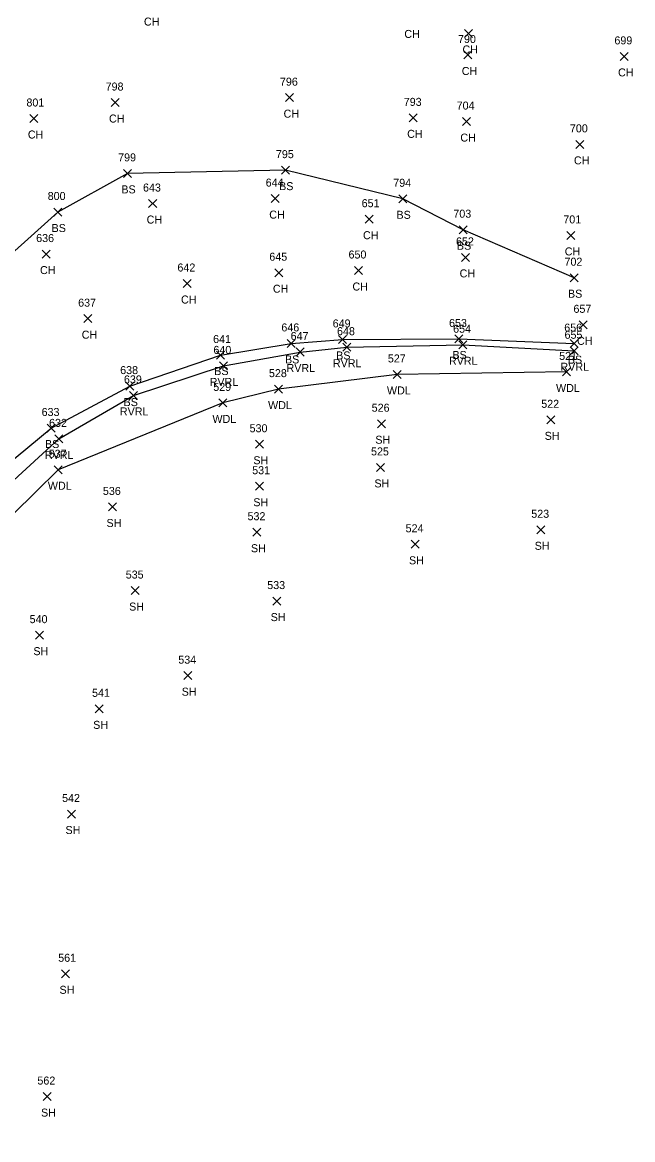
# Model space of a CAD drawing. Extents: x 1885914 to 1887218, y 756253 to 760620.
# Drawn here: x 1886903.9 to 1887056.2, y 759675.3 to 759954.5 of the extents above; entities that cross this region are included whole.
import ezdxf

# ---------------------------------------------------------------- set-up
doc = ezdxf.new("R2010")
doc.units = 0
for name, color, linetype in [('L_A', 7, 'Continuous'), ('L_I', 7, 'Continuous'), ('L_TIC', 7, 'Continuous'), ('LAWA', 7, 'Continuous'), ('LAWE', 7, 'Continuous'), ('LELB', 7, 'Continuous')]:
    doc.layers.add(name, color=color, linetype=linetype)

msp = doc.modelspace()

# ---------------------------------------------------------------- linework, layer by layer
at = {"layer": 'L_TIC'}
for points in [[(1887014.25, 759950.7), (1887016.25, 759952.7)], [(1887016.25, 759950.7), (1887014.25, 759952.7)], [(1887014.08, 759945.32), (1887016.08, 759947.32)], [(1887016.08, 759945.32), (1887014.08, 759947.32)], [(1887053.08, 759944.97), (1887055.08, 759946.97)], [(1887055.08, 759944.97), (1887053.08, 759946.97)], [(1886926.02, 759933.44), (1886928.02, 759935.44)], [(1886928.02, 759933.44), (1886926.02, 759935.44)], [(1886969.59, 759934.66), (1886971.59, 759936.66)], [(1886971.59, 759934.66), (1886969.59, 759936.66)], [(1886905.76, 759929.45), (1886907.76, 759931.45)], [(1886907.76, 759929.45), (1886905.76, 759931.45)], [(1887000.44, 759929.61), (1887002.44, 759931.61)], [(1887002.44, 759929.61), (1887000.44, 759931.61)], [(1887013.72, 759928.68), (1887015.72, 759930.68)], [(1887015.72, 759928.68), (1887013.72, 759930.68)], [(1887042.07, 759922.99), (1887044.07, 759924.99)], [(1887044.07, 759922.99), (1887042.07, 759924.99)], [(1886929.15, 759915.74), (1886931.15, 759917.74)], [(1886931.15, 759915.74), (1886929.15, 759917.74)], [(1886968.52, 759916.55), (1886970.52, 759918.55)], [(1886970.52, 759916.55), (1886968.52, 759918.55)], [(1886935.4, 759908.2), (1886937.4, 759910.2)], [(1886937.4, 759908.2), (1886935.4, 759910.2)], [(1886966.01, 759909.44), (1886968.01, 759911.44)], [(1886968.01, 759909.44), (1886966.01, 759911.44)], [(1886997.82, 759909.39), (1886999.82, 759911.39)], [(1886999.82, 759909.39), (1886997.82, 759911.39)], [(1886911.72, 759906.09), (1886913.72, 759908.09)], [(1886913.72, 759906.09), (1886911.72, 759908.09)], [(1886989.42, 759904.29), (1886991.42, 759906.29)], [(1886991.42, 759904.29), (1886989.42, 759906.29)], [(1887012.9, 759901.67), (1887014.9, 759903.67)], [(1887014.9, 759901.67), (1887012.9, 759903.67)], [(1887039.78, 759900.24), (1887041.78, 759902.24)], [(1887041.78, 759900.24), (1887039.78, 759902.24)], [(1886908.79, 759895.58), (1886910.79, 759897.58)], [(1886910.79, 759895.58), (1886908.79, 759897.58)], [(1887013.53, 759894.75), (1887015.53, 759896.75)], [(1887015.53, 759894.75), (1887013.53, 759896.75)], [(1886966.93, 759890.92), (1886968.93, 759892.92)], [(1886968.93, 759890.92), (1886966.93, 759892.92)], [(1886986.79, 759891.47), (1886988.79, 759893.47)], [(1886988.79, 759891.47), (1886986.79, 759893.47)], [(1886943.99, 759888.22), (1886945.99, 759890.22)], [(1886945.99, 759888.22), (1886943.99, 759890.22)], [(1887040.64, 759889.67), (1887042.64, 759891.67)], [(1887042.64, 759889.67), (1887040.64, 759891.67)], [(1886919.21, 759879.44), (1886921.21, 759881.44)], [(1886921.21, 759879.44), (1886919.21, 759881.44)], [(1887042.85, 759877.9), (1887044.85, 759879.9)], [(1887044.85, 759877.9), (1887042.85, 759879.9)], [(1886982.76, 759874.25), (1886984.76, 759876.25)], [(1886984.76, 759874.25), (1886982.76, 759876.25)], [(1887011.79, 759874.36), (1887013.79, 759876.36)], [(1887013.79, 759874.36), (1887011.79, 759876.36)], [(1886970, 759873.25), (1886972, 759875.25)], [(1886972, 759873.25), (1886970, 759875.25)], [(1886972.25, 759871.11), (1886974.25, 759873.11)], [(1886974.25, 759871.11), (1886972.25, 759873.11)], [(1886983.83, 759872.31), (1886985.83, 759874.31)], [(1886985.83, 759872.31), (1886983.83, 759874.31)], [(1887012.81, 759872.92), (1887014.81, 759874.92)], [(1887014.81, 759872.92), (1887012.81, 759874.92)], [(1887040.6, 759873.2), (1887042.6, 759875.2)], [(1887042.6, 759873.2), (1887040.6, 759875.2)], [(1887040.62, 759871.42), (1887042.62, 759873.42)], [(1887042.62, 759871.42), (1887040.62, 759873.42)], [(1886952.33, 759870.35), (1886954.33, 759872.35)], [(1886954.33, 759870.35), (1886952.33, 759872.35)], [(1886953.06, 759867.63), (1886955.06, 759869.63)], [(1886955.06, 759867.63), (1886953.06, 759869.63)], [(1886996.46, 759865.5), (1886998.46, 759867.5)], [(1886998.46, 759865.5), (1886996.46, 759867.5)], [(1887038.67, 759866.12), (1887040.67, 759868.12)], [(1887040.67, 759866.12), (1887038.67, 759868.12)], [(1886929.7, 759862.59), (1886931.7, 759864.59)], [(1886931.7, 759862.59), (1886929.7, 759864.59)], [(1886930.65, 759860.26), (1886932.65, 759862.26)], [(1886932.65, 759860.26), (1886930.65, 759862.26)], [(1886966.79, 759861.83), (1886968.79, 759863.83)], [(1886968.79, 759861.83), (1886966.79, 759863.83)], [(1886952.9, 759858.39), (1886954.9, 759860.39)], [(1886954.9, 759858.39), (1886952.9, 759860.39)], [(1886910.09, 759852.12), (1886912.09, 759854.12)], [(1886912.09, 759852.12), (1886910.09, 759854.12)], [(1886992.49, 759853.19), (1886994.49, 759855.19)], [(1886994.49, 759853.19), (1886992.49, 759855.19)], [(1887034.76, 759854.16), (1887036.76, 759856.16)], [(1887036.76, 759854.16), (1887034.76, 759856.16)], [(1886911.95, 759849.4), (1886913.95, 759851.4)], [(1886913.95, 759849.4), (1886911.95, 759851.4)], [(1886962.05, 759848.06), (1886964.05, 759850.06)], [(1886964.05, 759848.06), (1886962.05, 759850.06)], [(1886911.83, 759841.69), (1886913.83, 759843.69)], [(1886913.83, 759841.69), (1886911.83, 759843.69)], [(1886992.27, 759842.27), (1886994.27, 759844.27)], [(1886994.27, 759842.27), (1886992.27, 759844.27)], [(1886962.04, 759837.57), (1886964.04, 759839.57)], [(1886964.04, 759837.57), (1886962.04, 759839.57)], [(1886925.39, 759832.39), (1886927.39, 759834.39)], [(1886927.39, 759832.39), (1886925.39, 759834.39)], [(1887032.27, 759826.69), (1887034.27, 759828.69)], [(1887034.27, 759826.69), (1887032.27, 759828.69)], [(1886961.44, 759826.08), (1886963.44, 759828.08)], [(1886963.44, 759826.08), (1886961.44, 759828.08)], [(1887000.9, 759823.06), (1887002.9, 759825.06)], [(1887002.9, 759823.06), (1887000.9, 759825.06)], [(1886931.04, 759811.5), (1886933.04, 759813.5)], [(1886933.04, 759811.5), (1886931.04, 759813.5)], [(1886966.36, 759808.87), (1886968.36, 759810.87)], [(1886968.36, 759808.87), (1886966.36, 759810.87)], [(1886907.14, 759800.36), (1886909.14, 759802.36)], [(1886909.14, 759800.36), (1886907.14, 759802.36)], [(1886944.16, 759790.24), (1886946.16, 759792.24)], [(1886946.16, 759790.24), (1886944.16, 759792.24)], [(1886922.06, 759781.95), (1886924.06, 759783.95)], [(1886924.06, 759781.95), (1886922.06, 759783.95)], [(1886915.16, 759755.67), (1886917.16, 759757.67)], [(1886917.16, 759755.67), (1886915.16, 759757.67)], [(1886913.66, 759715.75), (1886915.66, 759717.75)], [(1886915.66, 759715.75), (1886913.66, 759717.75)], [(1886909.04, 759685.07), (1886911.04, 759687.07)], [(1886911.04, 759685.07), (1886909.04, 759687.07)]]:
    msp.add_lwpolyline(points, dxfattribs=at)
at = {"layer": 'LAWA'}
msp.add_lwpolyline([(1887039.67, 759867.12), (1886997.46, 759866.5), (1886967.79, 759862.83), (1886953.9, 759859.39), (1886912.83, 759842.69), (1886895.91, 759826.12), (1886876.51, 759800.34), (1886870.46, 759780.62), (1886866.61, 759757.15), (1886861.71, 759722.13), (1886864, 759684.51), (1886866.31, 759651.37), (1886872.7, 759617.94), (1886879.43, 759575.62), (1886888.58, 759548.75), (1886894.15, 759536.14), (1886894.58, 759504), (1886900.06, 759464.39)], dxfattribs=at)
at = {"layer": 'LAWE'}
msp.add_lwpolyline([(1886859.81, 759657.59), (1886858.79, 759683.07), (1886856.58, 759707.16), (1886854.34, 759720.31), (1886851.81, 759737.65), (1886851.21, 759747.56), (1886864.2, 759768.76), (1886870.14, 759791.05), (1886877.35, 759816.69), (1886896.62, 759835.46), (1886912.95, 759850.4), (1886931.65, 759861.26), (1886954.06, 759868.63), (1886973.25, 759872.11), (1886984.83, 759873.31), (1887013.81, 759873.92), (1887041.62, 759872.42)], dxfattribs=at)
at = {"layer": 'LELB'}
for points in [[(1887041.64, 759890.67), (1887013.9, 759902.67), (1886998.82, 759910.39), (1886969.52, 759917.55), (1886930.15, 759916.74), (1886912.72, 759907.09), (1886894.42, 759890.67), (1886880.9, 759884.96), (1886854.09, 759848.47), (1886840.08, 759816.36), (1886838.53, 759797.02), (1886821.58, 759765.7), (1886826.94, 759738), (1886825.11, 759733.57), (1886845.96, 759724.49), (1886848.98, 759700.26), (1886856.89, 759644.15), (1886862.57, 759606.59), (1886871.88, 759568.95), (1886881.65, 759535.15), (1886890.28, 759491.3), (1886901.49, 759441.86)], [(1886851.21, 759747.56), (1886859.63, 759770.26), (1886865.87, 759792.47), (1886875.45, 759817.63), (1886893.54, 759838.56), (1886911.09, 759853.12), (1886930.7, 759863.59), (1886953.33, 759871.35), (1886971, 759874.25), (1886983.76, 759875.25), (1887012.79, 759875.36), (1887041.6, 759874.2)]]:
    msp.add_lwpolyline(points, dxfattribs=at)

# ---------------------------------------------------------------- texts
at = {"layer": 'L_A'}
for s, p in [('CH', (1886934.22, 759953.67)), ('CH', (1886999.22, 759950.58)), ('CH', (1887013.74, 759946.7)), ('CH', (1887013.56, 759941.32)), ('CH', (1887052.57, 759940.97)), ('CH', (1886969.08, 759930.66)), ('CH', (1886925.51, 759929.44)), ('CH', (1886905.25, 759925.45)), ('CH', (1886999.93, 759925.61)), ('CH', (1887013.21, 759924.68)), ('CH', (1887041.56, 759918.99)), ('BS', (1886928.59, 759911.74)), ('BS', (1886967.96, 759912.55)), ('CH', (1886965.5, 759905.44)), ('BS', (1886997.26, 759905.39)), ('BS', (1886911.17, 759902.09)), ('CH', (1886934.89, 759904.2)), ('CH', (1886988.91, 759900.29)), ('BS', (1887012.35, 759897.67)), ('CH', (1887039.27, 759896.24)), ('CH', (1886908.28, 759891.58)), ('CH', (1887013.02, 759890.75)), ('CH', (1886966.41, 759886.92)), ('CH', (1886986.27, 759887.47)), ('BS', (1887040.08, 759885.67)), ('CH', (1886943.48, 759884.22)), ('CH', (1886918.69, 759875.44)), ('CH', (1887042.33, 759873.9)), ('BS', (1886969.44, 759869.25)), ('RVRL', (1886981.4, 759868.31)), ('BS', (1886982.2, 759870.25)), ('RVRL', (1887010.37, 759868.92)), ('BS', (1887011.23, 759870.36)), ('BS', (1887040.04, 759869.2)), ('BS', (1886951.77, 759866.35)), ('RVRL', (1886969.82, 759867.11)), ('RVRL', (1887038.19, 759867.42)), ('RVRL', (1886950.63, 759863.63)), ('WDL', (1886994.88, 759861.5)), ('WDL', (1887037.09, 759862.12)), ('BS', (1886929.14, 759858.59)), ('WDL', (1886965.21, 759857.83)), ('RVRL', (1886928.22, 759856.26)), ('WDL', (1886951.32, 759854.39)), ('SH', (1886991.98, 759849.19)), ('SH', (1887034.25, 759850.16)), ('BS', (1886909.53, 759848.12)), ('RVRL', (1886909.51, 759845.4)), ('SH', (1886961.54, 759844.06)), ('WDL', (1886910.24, 759837.69)), ('SH', (1886991.76, 759838.27)), ('SH', (1886961.53, 759833.57)), ('SH', (1886924.88, 759828.39)), ('SH', (1886960.93, 759822.08)), ('SH', (1887031.76, 759822.69)), ('SH', (1887000.39, 759819.06)), ('SH', (1886930.53, 759807.5)), ('SH', (1886965.85, 759804.87)), ('SH', (1886906.63, 759796.36)), ('SH', (1886943.65, 759786.24)), ('SH', (1886921.55, 759777.95)), ('SH', (1886914.64, 759751.67)), ('SH', (1886913.15, 759711.75)), ('SH', (1886908.53, 759681.07))]:
    msp.add_text(s, height=2, dxfattribs=at).set_placement(p)
at = {"layer": 'L_I'}
for s, p in [('790', (1887012.63, 759949.32)), ('699', (1887051.66, 759948.97)), ('796', (1886968.17, 759938.66)), ('798', (1886924.66, 759937.44)), ('801', (1886904.89, 759933.45)), ('793', (1886999.08, 759933.61)), ('704', (1887012.28, 759932.68)), ('700', (1887040.55, 759926.99)), ('799', (1886927.78, 759919.74)), ('795', (1886967.16, 759920.55)), ('644', (1886964.61, 759913.44)), ('794', (1886996.46, 759913.39)), ('800', (1886910.2, 759910.09)), ('643', (1886933.99, 759912.2)), ('651', (1886988.57, 759908.29)), ('703', (1887011.46, 759905.67)), ('701', (1887038.91, 759904.24)), ('636', (1886907.32, 759899.58)), ('652', (1887012.12, 759898.75)), ('645', (1886965.52, 759894.92)), ('650', (1886985.29, 759895.47)), ('702', (1887039.2, 759893.67)), ('642', (1886942.58, 759892.22)), ('637', (1886917.8, 759883.44)), ('657', (1887041.44, 759881.9)), ('646', (1886968.53, 759877.25)), ('649', (1886981.34, 759878.25)), ('653', (1887010.38, 759878.36)), ('654', (1887011.4, 759876.92)), ('656', (1887039.14, 759877.2)), ('641', (1886951.49, 759874.35)), ('647', (1886970.84, 759875.11)), ('648', (1886982.42, 759876.31)), ('655', (1887039.21, 759875.42)), ('640', (1886951.57, 759871.63)), ('527', (1886995.1, 759869.5)), ('521', (1887037.87, 759870.12)), ('638', (1886928.29, 759866.59)), ('528', (1886965.43, 759865.83)), ('639', (1886929.23, 759864.26)), ('529', (1886951.53, 759862.39)), ('526', (1886991.07, 759857.19)), ('522', (1887033.4, 759858.16)), ('633', (1886908.68, 759856.12)), ('632', (1886910.54, 759853.4)), ('530', (1886960.6, 759852.06)), ('525', (1886990.91, 759846.27)), ('537', (1886910.46, 759845.69)), ('531', (1886961.24, 759841.57)), ('536', (1886923.98, 759836.39)), ('532', (1886960.08, 759830.08)), ('523', (1887030.91, 759830.69)), ('524', (1886999.54, 759827.06)), ('535', (1886929.68, 759815.5)), ('533', (1886965, 759812.87)), ('540', (1886905.69, 759804.36)), ('534', (1886942.8, 759794.24)), ('541', (1886921.27, 759785.95)), ('542', (1886913.79, 759759.67)), ('561', (1886912.82, 759719.75)), ('562', (1886907.63, 759689.07))]:
    msp.add_text(s, height=2, dxfattribs=at).set_placement(p)

doc.saveas('drawing.dxf')
